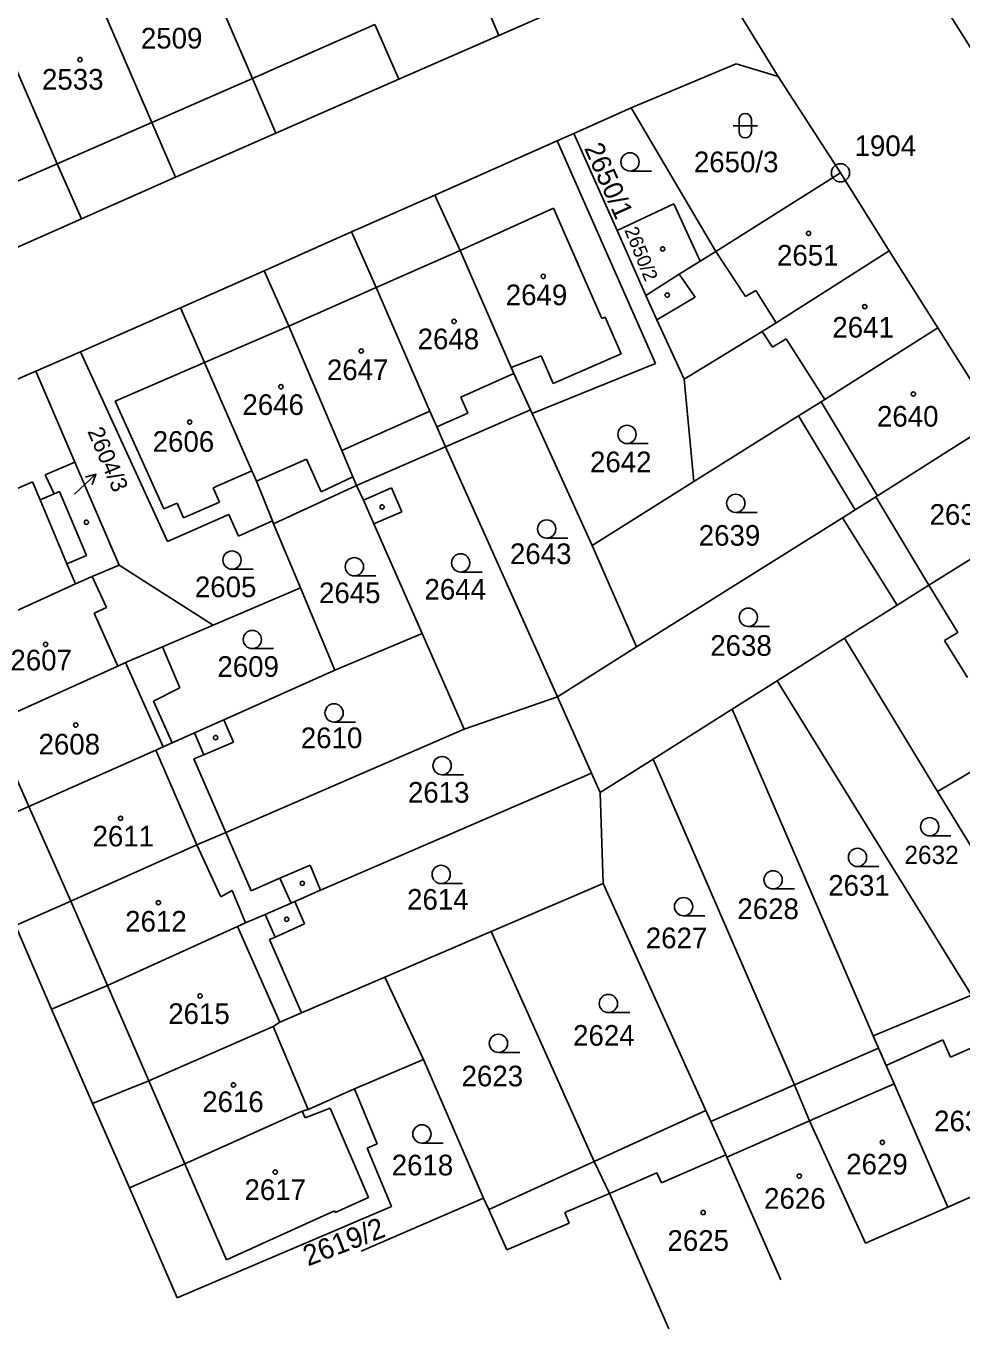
# Model space of a CAD drawing. Extents: x -822293 to -820259, y -1071573 to -1068794.
# Drawn here: x -820749.9 to -820673, y -1071339.5 to -1071232.4 of the extents above; entities that cross this region are included whole.
import ezdxf

# ---------------------------------------------------------------- set-up
doc = ezdxf.new("R2010")
doc.units = 0
for name, color, linetype in [('Vrstva 1', 7, 'Continuous'), ('Vrstva 16', 7, 'Continuous'), ('Vrstva 17', 7, 'Continuous'), ('Vrstva 18', 7, 'Continuous'), ('Vrstva 19', 7, 'Continuous'), ('Vrstva 2', 7, 'Continuous'), ('Vrstva 24', 7, 'Continuous'), ('Vrstva 25', 7, 'Continuous'), ('Vrstva 29', 7, 'Continuous'), ('Vrstva 3', 7, 'Continuous'), ('Vrstva 4', 7, 'Continuous')]:
    doc.layers.add(name, color=color, linetype=linetype)

msp = doc.modelspace()

# ---------------------------------------------------------------- linework, layer by layer
at = {"layer": 'Vrstva 1'}
for p, q in [((-820622.76, -1071313.08), (-820677.95, -1071225.19)), ((-820711.07, -1071233.22), (-820699.66, -1071228.17)), ((-820688.09, -1071236.58), (-820693.68, -1071227.51)), ((-820712.97, -1071228.69), (-820711.07, -1071233.22)), ((-820719.29, -1071236.82), (-820721.25, -1071232.32)), ((-820719.29, -1071236.82), (-820711.07, -1071233.22)), ((-820700.17, -1071239.16), (-820691.56, -1071235.54)), ((-820691.56, -1071235.54), (-820688.09, -1071236.58)), ((-820731.32, -1071236.74), (-820729.39, -1071241.25)), ((-820729.39, -1071241.25), (-820719.29, -1071236.82)), ((-820688.09, -1071236.58), (-820682.97, -1071244.51)), ((-820704.89, -1071241.27), (-820700.17, -1071239.16)), ((-820700.17, -1071239.16), (-820693.22, -1071250.97)), ((-820737.63, -1071244.87), (-820739.57, -1071240.36)), ((-820737.63, -1071244.87), (-820729.39, -1071241.25)), ((-820716.32, -1071246.34), (-820706.26, -1071241.88)), ((-820706.26, -1071241.88), (-820704.89, -1071241.27)), ((-820706.26, -1071241.88), (-820698.18, -1071260.18)), ((-820704.89, -1071241.27), (-820701.34, -1071249.26)), ((-820747.36, -1071243.77), (-820745.37, -1071248.28)), ((-820745.37, -1071248.28), (-820737.63, -1071244.87)), ((-820716.32, -1071246.34), (-820723.16, -1071249.37)), ((-820714.24, -1071250.9), (-820716.32, -1071246.34)), ((-820752.2, -1071251.29), (-820745.37, -1071248.28)), ((-820723.16, -1071249.37), (-820730.34, -1071252.56)), ((-820723.16, -1071249.37), (-820721.13, -1071253.93)), ((-820694.5, -1071251.77), (-820693.22, -1071250.97)), ((-820730.34, -1071252.56), (-820737.23, -1071255.6)), ((-820730.34, -1071252.56), (-820728.33, -1071257.1)), ((-820737.23, -1071255.6), (-820745.44, -1071259.22)), ((-820737.23, -1071255.6), (-820735.24, -1071260.1)), ((-820698.08, -1071256.59), (-820695.83, -1071261.47)), ((-820695.83, -1071261.47), (-820689.4, -1071257.55)), ((-820745.44, -1071259.22), (-820749.12, -1071260.8)), ((-820745.44, -1071259.22), (-820738.29, -1071274.8)), ((-820698.18, -1071260.18), (-820708.32, -1071264.29)), ((-820767.46, -1071268.84), (-820749.12, -1071260.8)), ((-820749.12, -1071260.8), (-820745.91, -1071268.3)), ((-820708.45, -1071264), (-820709.83, -1071260.99)), ((-820695.83, -1071261.47), (-820695.03, -1071269.89)), ((-820686.43, -1071264.49), (-820684.56, -1071263.32)), ((-820715.43, -1071267.03), (-820708.45, -1071264)), ((-820708.32, -1071264.29), (-820708.45, -1071264)), ((-820703.38, -1071275.13), (-820708.32, -1071264.29)), ((-820695.03, -1071269.89), (-820686.43, -1071264.49)), ((-820686.43, -1071264.49), (-820681.76, -1071272.2)), ((-820716.16, -1071265.39), (-820715.43, -1071267.03)), ((-820722.76, -1071270.2), (-820715.43, -1071267.03)), ((-820715.43, -1071267.03), (-820706.24, -1071287.59)), ((-820730.99, -1071269.84), (-820729.66, -1071273.12)), ((-820723.05, -1071269.5), (-820722.76, -1071270.2)), ((-820703.38, -1071275.13), (-820695.03, -1071269.89)), ((-820748.77, -1071271.39), (-820747.62, -1071270.9)), ((-820729.57, -1071273.35), (-820722.76, -1071270.2)), ((-820722.76, -1071270.2), (-820722.18, -1071271.42)), ((-820680.06, -1071271.14), (-820681.76, -1071272.2)), ((-820722.18, -1071271.42), (-820721.32, -1071273.37)), ((-820681.76, -1071272.2), (-820682.81, -1071272.87)), ((-820738.29, -1071274.8), (-820733.26, -1071272.58)), ((-820733.26, -1071272.58), (-820732.47, -1071274.36)), ((-820732.47, -1071274.36), (-820729.66, -1071273.12)), ((-820729.66, -1071273.12), (-820729.57, -1071273.35)), ((-820682.81, -1071272.87), (-820699.73, -1071283.48)), ((-820682.81, -1071272.87), (-820678.31, -1071280.04)), ((-820729.57, -1071273.35), (-820727.37, -1071278.63)), ((-820721.32, -1071273.37), (-820717.36, -1071282.38)), ((-820699.73, -1071283.48), (-820703.38, -1071275.13)), ((-820742.28, -1071276.75), (-820734.54, -1071281.69)), ((-820734.54, -1071281.69), (-820727.37, -1071278.63)), ((-820727.37, -1071278.63), (-820724.55, -1071285.39)), ((-820678.31, -1071280.04), (-820675.71, -1071278.4)), ((-820682.65, -1071282.77), (-820678.31, -1071280.04)), ((-820734.54, -1071281.69), (-820738.71, -1071283.48)), ((-820724.55, -1071285.39), (-820717.36, -1071282.38)), ((-820717.36, -1071282.38), (-820713.9, -1071290.24)), ((-820688.19, -1071286.27), (-820682.65, -1071282.77)), ((-820674.99, -1071295.36), (-820682.65, -1071282.77)), ((-820738.71, -1071283.48), (-820741.75, -1071284.76)), ((-820738.71, -1071283.48), (-820737.29, -1071286.84)), ((-820699.73, -1071283.48), (-820706.24, -1071287.59)), ((-820724.55, -1071285.39), (-820733.66, -1071289.48)), ((-820737.29, -1071286.84), (-820739.45, -1071287.95)), ((-820691.87, -1071288.59), (-820688.19, -1071286.27)), ((-820688.19, -1071286.27), (-820672.2, -1071312.09)), ((-820739.45, -1071287.95), (-820737.91, -1071291.37)), ((-820713.9, -1071290.24), (-820706.24, -1071287.59)), ((-820706.24, -1071287.59), (-820703.44, -1071293.85)), ((-820698.38, -1071292.7), (-820691.87, -1071288.59)), ((-820691.87, -1071288.59), (-820680.29, -1071315.45)), ((-820713.9, -1071290.24), (-820733.51, -1071298.72)), ((-820737.91, -1071291.37), (-820738.66, -1071291.7)), ((-820736.08, -1071290.55), (-820737.91, -1071291.37)), ((-820667.84, -1071291.16), (-820674.99, -1071295.36)), ((-820735.32, -1071292.35), (-820736.13, -1071292.69)), ((-820736.13, -1071292.69), (-820733.51, -1071298.72)), ((-820702.73, -1071295.45), (-820698.38, -1071292.7)), ((-820698.38, -1071292.7), (-820686.75, -1071319.48)), ((-820725.71, -1071303.48), (-820703.44, -1071293.85)), ((-820703.44, -1071293.85), (-820702.73, -1071295.45)), ((-820702.73, -1071295.45), (-820702.49, -1071302.92)), ((-820674.99, -1071295.36), (-820666.24, -1071309.73)), ((-820749.69, -1071296.59), (-820754.26, -1071298.59)), ((-820733.51, -1071298.72), (-820735.87, -1071299.74)), ((-820731.42, -1071303.52), (-820733.51, -1071298.72)), ((-820729.05, -1071302.49), (-820731.42, -1071303.52)), ((-820702.49, -1071302.92), (-820711.68, -1071306.87)), ((-820702.49, -1071302.92), (-820694.04, -1071321.59)), ((-820746.25, -1071304.37), (-820750.8, -1071306.39)), ((-820731.89, -1071306.16), (-820730.27, -1071305.46)), ((-820750.8, -1071306.39), (-820747.82, -1071313.25)), ((-820729.91, -1071307.54), (-820729.45, -1071307.33)), ((-820727.28, -1071313.55), (-820729.91, -1071307.54)), ((-820711.68, -1071306.87), (-820720.44, -1071310.62)), ((-820711.68, -1071306.87), (-820703.23, -1071325.77)), ((-820720.44, -1071310.62), (-820727.28, -1071313.55)), ((-820720.44, -1071310.62), (-820717.26, -1071317.38)), ((-820747.82, -1071313.25), (-820743.23, -1071311.31)), ((-820672.2, -1071312.09), (-820680.29, -1071315.45)), ((-820747.82, -1071313.25), (-820744.45, -1071321.01)), ((-820729.07, -1071314.32), (-820727.28, -1071313.55)), ((-820680.29, -1071315.45), (-820679.85, -1071316.45)), ((-820679.85, -1071316.45), (-820686.75, -1071319.48)), ((-820679.23, -1071317.88), (-820679.85, -1071316.45)), ((-820717.26, -1071317.38), (-820722.93, -1071319.81)), ((-820717.26, -1071317.38), (-820712.31, -1071328.8)), ((-820744.45, -1071321.01), (-820739.83, -1071319.14)), ((-820722.93, -1071319.81), (-820726.74, -1071321.49)), ((-820721.05, -1071324.33), (-820722.93, -1071319.81)), ((-820686.75, -1071319.48), (-820693.63, -1071322.49)), ((-820685.53, -1071322.44), (-820686.75, -1071319.48)), ((-820744.45, -1071321.01), (-820741.43, -1071327.94)), ((-820694.04, -1071321.59), (-820703.23, -1071325.77)), ((-820693.63, -1071322.49), (-820694.04, -1071321.59)), ((-820692.39, -1071325.23), (-820693.63, -1071322.49)), ((-820721.88, -1071324.68), (-820721.05, -1071324.33)), ((-820719.88, -1071329.48), (-820721.88, -1071324.68)), ((-820711.89, -1071329.72), (-820703.23, -1071325.77)), ((-820703.23, -1071325.77), (-820701.96, -1071328.4)), ((-820736.86, -1071325.98), (-820741.43, -1071327.94)), ((-820741.43, -1071327.94), (-820737.51, -1071336.97)), ((-820712.31, -1071328.8), (-820722.38, -1071333.16)), ((-820712.31, -1071328.8), (-820711.89, -1071329.72)), ((-820737.51, -1071336.97), (-820719.88, -1071329.48)), ((-820711.89, -1071329.72), (-820710.4, -1071333.04))]:
    msp.add_line(p, q, dxfattribs=at)
at = {"layer": 'Vrstva 16'}
msp.add_line((-820745.93, -1071270.92), (-820744.178, -1071269.28), dxfattribs=at)
msp.add_lwpolyline([(-820745.036, -1071269.534), (-820744.178, -1071269.28), (-820744.489, -1071270.118)], dxfattribs=at)
at = {"layer": 'Vrstva 2'}
for p, q in [((-820735.94, -1071226.03), (-820731.32, -1071236.74)), ((-820739.57, -1071240.36), (-820744.25, -1071229.56)), ((-820751.92, -1071233.24), (-820747.36, -1071243.77)), ((-820693.22, -1071250.97), (-820682.97, -1071244.51)), ((-820682.97, -1071244.51), (-820678.97, -1071250.92)), ((-820701.34, -1071249.26), (-820696.68, -1071247.06)), ((-820696.68, -1071247.06), (-820694.5, -1071251.77)), ((-820698.97, -1071254.58), (-820701.34, -1071249.26)), ((-820710.04, -1071260.52), (-820714.24, -1071250.9)), ((-820694.5, -1071251.77), (-820696.23, -1071252.85)), ((-820688.27, -1071256.84), (-820678.97, -1071250.92)), ((-820678.97, -1071250.92), (-820674.96, -1071257.25)), ((-820696.23, -1071252.85), (-820698.97, -1071254.58)), ((-820721.13, -1071253.93), (-820716.73, -1071264.1)), ((-820698.97, -1071254.58), (-820698.08, -1071256.59)), ((-820728.33, -1071257.1), (-820723.97, -1071267.34)), ((-820689.4, -1071257.55), (-820688.27, -1071256.84)), ((-820684.27, -1071263.14), (-820674.96, -1071257.25)), ((-820674.96, -1071257.25), (-820670.17, -1071264.87)), ((-820735.24, -1071260.1), (-820731.35, -1071269.01)), ((-820709.83, -1071260.99), (-820710.04, -1071260.52)), ((-820684.56, -1071263.32), (-820684.27, -1071263.14)), ((-820716.73, -1071264.1), (-820716.16, -1071265.39)), ((-820670.17, -1071264.87), (-820679.93, -1071271.06)), ((-820723.97, -1071267.34), (-820723.05, -1071269.5)), ((-820748.34, -1071269.34), (-820745.91, -1071268.3)), ((-820745.91, -1071268.3), (-820742.28, -1071276.75)), ((-820731.35, -1071269.01), (-820730.99, -1071269.84)), ((-820759.64, -1071274.41), (-820749.39, -1071269.91)), ((-820749.39, -1071269.91), (-820748.77, -1071271.39)), ((-820747.62, -1071270.9), (-820748.34, -1071269.34)), ((-820747.62, -1071270.9), (-820747.16, -1071270.71)), ((-820747.16, -1071270.71), (-820744.95, -1071275.96)), ((-820679.93, -1071271.06), (-820680.06, -1071271.14)), ((-820675.71, -1071278.4), (-820665.69, -1071272.14)), ((-820744.95, -1071275.96), (-820746.56, -1071276.64)), ((-820746.56, -1071276.64), (-820745.86, -1071278.3)), ((-820742.28, -1071276.75), (-820744.49, -1071277.7)), ((-820745.86, -1071278.3), (-820755.79, -1071282.82)), ((-820744.49, -1071277.7), (-820745.86, -1071278.3)), ((-820742.39, -1071285.05), (-820752.73, -1071289.74)), ((-820741.75, -1071284.76), (-820742.39, -1071285.05)), ((-820733.66, -1071289.48), (-820736.08, -1071290.55)), ((-820733.66, -1071289.48), (-820732.88, -1071291.32)), ((-820732.88, -1071291.32), (-820735.32, -1071292.35)), ((-820739.25, -1071291.96), (-820749.69, -1071296.59)), ((-820738.66, -1071291.7), (-820739.25, -1071291.96)), ((-820735.87, -1071299.74), (-820746.25, -1071304.37)), ((-820726.58, -1071301.41), (-820729.05, -1071302.49)), ((-820725.71, -1071303.48), (-820726.58, -1071301.41)), ((-820727.84, -1071304.41), (-820725.71, -1071303.48)), ((-820730.27, -1071305.46), (-820728.13, -1071304.54)), ((-820728.13, -1071304.54), (-820727.84, -1071304.41)), ((-820727.04, -1071306.24), (-820727.84, -1071304.41)), ((-820743.23, -1071311.31), (-820732.54, -1071306.45)), ((-820732.54, -1071306.45), (-820731.89, -1071306.16)), ((-820729.45, -1071307.33), (-820727.04, -1071306.24)), ((-820739.83, -1071319.14), (-820729.62, -1071314.67)), ((-820729.62, -1071314.67), (-820729.07, -1071314.32)), ((-820678.57, -1071319.39), (-820679.23, -1071317.88)), ((-820674.14, -1071329.52), (-820678.57, -1071319.39)), ((-820726.74, -1071321.49), (-820727.22, -1071321.65)), ((-820727.22, -1071321.65), (-820736.86, -1071325.98)), ((-820680.91, -1071332.5), (-820685.53, -1071322.44)), ((-820692.31, -1071325.41), (-820692.39, -1071325.23)), ((-820687.88, -1071335.5), (-820692.31, -1071325.41)), ((-820665.87, -1071325.89), (-820674.14, -1071329.52)), ((-820701.96, -1071328.4), (-820697.07, -1071339.54)), ((-820674.14, -1071329.52), (-820680.91, -1071332.5))]:
    msp.add_line(p, q, dxfattribs=at)
at = {"layer": 'Vrstva 24'}
for radius in [0.75, 0.0327]:
    msp.add_circle((-820682.97, -1071244.51), radius, dxfattribs=at)
at = {"layer": 'Vrstva 25'}
for p, q in [((-820691.3, -1071241.131), (-820691.3, -1071240.131)), ((-820690.3, -1071241.131), (-820690.3, -1071240.131)), ((-820691.8, -1071240.631), (-820689.8, -1071240.631)), ((-820698.52, -1071244.36), (-820700.27, -1071244.36)), ((-820698.77, -1071266.76), (-820700.52, -1071266.76)), ((-820689.83, -1071272.42), (-820691.58, -1071272.42)), ((-820705.38, -1071274.53), (-820707.13, -1071274.53)), ((-820731.24, -1071277.09), (-820732.99, -1071277.09)), ((-820712.44, -1071277.32), (-820714.19, -1071277.32)), ((-820721.18, -1071277.64), (-820722.93, -1071277.64)), ((-820688.8, -1071281.79), (-820690.55, -1071281.79)), ((-820729.57, -1071283.62), (-820731.32, -1071283.62)), ((-820722.85, -1071289.65), (-820724.6, -1071289.65)), ((-820713.97, -1071293.99), (-820715.72, -1071293.99)), ((-820673.89, -1071299.01), (-820675.64, -1071299.01)), ((-820679.82, -1071301.53), (-820681.57, -1071301.53)), ((-820714.05, -1071302.93), (-820715.8, -1071302.93)), ((-820686.76, -1071303.37), (-820688.51, -1071303.37)), ((-820694.12, -1071305.58), (-820695.87, -1071305.58)), ((-820700.3, -1071313.54), (-820702.05, -1071313.54)), ((-820709.34, -1071316.81), (-820711.09, -1071316.81)), ((-820715.63, -1071324.26), (-820717.38, -1071324.26))]:
    msp.add_line(p, q, dxfattribs=at)
for centre, radius in [((-820745.49, -1071235.2), 0.175), ((-820700.27, -1071243.61), 0.75), ((-820685.6, -1071249.48), 0.175), ((-820697.59, -1071250.76), 0.175), ((-820707.41, -1071253.02), 0.175), ((-820697.21, -1071254.56), 0.175), ((-820680.98, -1071255.51), 0.175), ((-820714.73, -1071256.72), 0.175), ((-820722.37, -1071259.15), 0.175), ((-820728.97, -1071262.09), 0.175), ((-820676.98, -1071262.69), 0.175), ((-820736.47, -1071265), 0.175), ((-820700.52, -1071266.01), 0.75), ((-820691.58, -1071271.67), 0.75), ((-820744.96, -1071273.23), 0.175), ((-820707.13, -1071273.78), 0.75), ((-820732.99, -1071276.34), 0.75), ((-820722.93, -1071276.89), 0.75), ((-820714.19, -1071276.57), 0.75), ((-820690.55, -1071281.04), 0.75), ((-820731.32, -1071282.87), 0.75), ((-820748.32, -1071283.27), 0.175), ((-820724.6, -1071288.9), 0.75), ((-820745.84, -1071289.9), 0.175), ((-820734.34, -1071290.93), 0.175), ((-820715.72, -1071293.24), 0.75), ((-820742.15, -1071297.57), 0.175), ((-820675.64, -1071298.26), 0.75), ((-820681.57, -1071300.78), 0.75), ((-820715.8, -1071302.18), 0.75), ((-820688.51, -1071302.62), 0.75), ((-820727.21, -1071302.91), 0.175), ((-820739.04, -1071304.5), 0.175), ((-820695.87, -1071304.83), 0.75), ((-820728.5, -1071305.86), 0.175), ((-820735.61, -1071312.16), 0.175), ((-820702.05, -1071312.79), 0.75), ((-820711.09, -1071316.06), 0.75), ((-820732.87, -1071319.48), 0.175), ((-820717.38, -1071323.51), 0.75), ((-820679.53, -1071324.21), 0.175), ((-820729.44, -1071326.65), 0.175), ((-820686.36, -1071326.98), 0.175), ((-820694.26, -1071329.97), 0.175)]:
    msp.add_circle(centre, radius, dxfattribs=at)
for centre, start, end in [((-820690.8, -1071240.131), 0, 180), ((-820690.8, -1071241.131), 180, 0)]:
    msp.add_arc(centre, 0.5, start, end, dxfattribs=at)
at = {"layer": 'Vrstva 29'}
msp.add_circle((-820720.65, -1071271.97), 0.175, dxfattribs=at)
at = {"layer": 'Vrstva 3'}
for p, q in [((-820721.25, -1071232.32), (-820731.32, -1071236.74)), ((-820731.32, -1071236.74), (-820739.57, -1071240.36)), ((-820739.57, -1071240.36), (-820747.36, -1071243.77)), ((-820747.36, -1071243.77), (-820754.18, -1071246.75)), ((-820714.24, -1071250.9), (-820706.56, -1071247.41)), ((-820702.6, -1071256.49), (-820706.56, -1071247.41)), ((-820721.13, -1071253.93), (-820714.24, -1071250.9)), ((-820693.22, -1071250.97), (-820690.78, -1071254.68)), ((-820696.23, -1071252.85), (-820694.92, -1071254.72)), ((-820728.33, -1071257.1), (-820721.13, -1071253.93)), ((-820694.92, -1071254.72), (-820698.08, -1071256.59)), ((-820690.78, -1071254.68), (-820689.94, -1071254.17)), ((-820689.94, -1071254.17), (-820688.27, -1071256.84)), ((-820735.24, -1071260.1), (-820728.33, -1071257.1)), ((-820702.32, -1071256.37), (-820702.6, -1071256.49)), ((-820701.01, -1071259.39), (-820702.32, -1071256.37)), ((-820689.4, -1071257.55), (-820688.56, -1071258.83)), ((-820688.56, -1071258.83), (-820687.44, -1071258.16)), ((-820687.44, -1071258.16), (-820684.27, -1071263.14)), ((-820706.59, -1071261.82), (-820701.01, -1071259.39)), ((-820742.61, -1071263.29), (-820735.24, -1071260.1)), ((-820710.04, -1071260.52), (-820707.58, -1071259.54)), ((-820707.58, -1071259.54), (-820706.59, -1071261.82)), ((-820714.19, -1071262.94), (-820709.83, -1071260.99)), ((-820742.61, -1071263.29), (-820738.6, -1071272.14)), ((-820713.6, -1071264.25), (-820714.19, -1071262.94)), ((-820684.56, -1071263.32), (-820679.93, -1071271.06)), ((-820723.97, -1071267.34), (-820716.73, -1071264.1)), ((-820716.16, -1071265.39), (-820713.6, -1071264.25)), ((-820734.54, -1071270.39), (-820731.35, -1071269.01)), ((-820730.99, -1071269.84), (-820726.88, -1071268.05)), ((-820726.88, -1071268.05), (-820725.67, -1071270.74)), ((-820725.67, -1071270.74), (-820723.05, -1071269.5)), ((-820734.03, -1071271.58), (-820734.54, -1071270.39)), ((-820680.06, -1071271.14), (-820675.71, -1071278.4)), ((-820746.56, -1071276.64), (-820748.77, -1071271.39)), ((-820738.6, -1071272.14), (-820737.51, -1071271.67)), ((-820737.51, -1071271.67), (-820736.99, -1071272.86)), ((-820736.99, -1071272.86), (-820734.03, -1071271.58)), ((-820744.49, -1071277.7), (-820743.3, -1071280.24)), ((-820675.71, -1071278.4), (-820673.32, -1071282.3)), ((-820743.3, -1071280.24), (-820744.32, -1071280.7)), ((-820744.32, -1071280.7), (-820742.39, -1071285.05)), ((-820673.32, -1071282.3), (-820674.43, -1071282.94)), ((-820674.43, -1071282.94), (-820672.52, -1071285.99)), ((-820741.75, -1071284.76), (-820738.66, -1071291.7)), ((-820749.69, -1071296.59), (-820752.73, -1071289.74)), ((-820736.08, -1071290.55), (-820735.32, -1071292.35)), ((-820739.25, -1071291.96), (-820735.87, -1071299.74)), ((-820746.25, -1071304.37), (-820749.69, -1071296.59)), ((-820735.87, -1071299.74), (-820733.9, -1071304.01)), ((-820729.05, -1071302.49), (-820728.13, -1071304.54)), ((-820743.23, -1071311.31), (-820746.25, -1071304.37)), ((-820733.9, -1071304.01), (-820732.98, -1071303.51)), ((-820732.98, -1071303.51), (-820731.89, -1071306.16)), ((-820730.27, -1071305.46), (-820729.45, -1071307.33)), ((-820732.54, -1071306.45), (-820729.07, -1071314.32)), ((-820739.83, -1071319.14), (-820743.23, -1071311.31)), ((-820729.62, -1071314.67), (-820726.74, -1071321.49)), ((-820679.23, -1071317.88), (-820674.56, -1071315.78)), ((-820674.56, -1071315.78), (-820673.92, -1071317.2)), ((-820673.92, -1071317.2), (-820670.53, -1071315.69)), ((-820736.86, -1071325.98), (-820739.83, -1071319.14)), ((-820685.53, -1071322.44), (-820678.57, -1071319.39)), ((-820726.97, -1071322.2), (-820724.93, -1071321.38)), ((-820724.93, -1071321.38), (-820721.78, -1071328.73)), ((-820727.22, -1071321.65), (-820726.97, -1071322.2)), ((-820692.31, -1071325.41), (-820685.53, -1071322.44)), ((-820697.68, -1071327.52), (-820692.39, -1071325.23)), ((-820733.44, -1071333.86), (-820736.86, -1071325.98)), ((-820701.96, -1071328.4), (-820698.06, -1071326.7)), ((-820698.06, -1071326.7), (-820697.68, -1071327.52)), ((-820721.78, -1071328.73), (-820724.5, -1071329.96)), ((-820705.64, -1071329.97), (-820701.96, -1071328.4)), ((-820724.56, -1071329.83), (-820733.44, -1071333.86)), ((-820724.5, -1071329.96), (-820724.56, -1071329.83)), ((-820705.27, -1071330.85), (-820705.64, -1071329.97)), ((-820710.4, -1071333.04), (-820705.27, -1071330.85))]:
    msp.add_line(p, q, dxfattribs=at)
at = {"layer": 'Vrstva 4'}
for p, q in [((-820722.18, -1071271.42), (-820719.89, -1071270.41)), ((-820719.89, -1071270.41), (-820719.03, -1071272.36)), ((-820719.03, -1071272.36), (-820721.32, -1071273.37))]:
    msp.add_line(p, q, dxfattribs=at)

# ---------------------------------------------------------------- texts
at = {"layer": 'Vrstva 16'}
for s, height, rotation, p in [('2604/3', 1.36, 293.01563, (-820744.9, -1071265.75)), ('2619/2', 1.7, 21.08564, (-820726.75, -1071334.41))]:
    msp.add_text(s, height=height, rotation=rotation, dxfattribs=at).set_placement(p)
at = {"layer": 'Vrstva 17'}
msp.add_text('1904', height=1.7, dxfattribs=at).set_placement((-820681.815, -1071243.13))
at = {"layer": 'Vrstva 18'}
msp.add_text('2650/1', height=1.6, rotation=293.95575, dxfattribs=at).set_placement((-820704.069, -1071242.471))
for s, height, p in [('2650/3', 1.7, (-820695.024, -1071244.46)), ('2642', 1.7, (-820703.562, -1071269.12)), ('2639', 1.7, (-820694.624, -1071275.16)), ('2643', 1.7, (-820710.144, -1071276.67)), ('2605', 1.7, (-820736.042, -1071279.39)), ('2645', 1.7, (-820725.839, -1071279.88)), ('2644', 1.7, (-820717.168, -1071279.59)), ('2638', 1.7, (-820693.678, -1071284.21)), ('2609', 1.7, (-820734.192, -1071285.94)), ('2610', 1.7, (-820727.334, -1071291.8)), ('2613', 1.7, (-820718.528, -1071296.28)), ('2632', 1.5, (-820677.718, -1071301.32)), ('2631', 1.7, (-820683.978, -1071303.93)), ('2614', 1.7, (-820718.6, -1071305.08)), ('2628', 1.7, (-820691.446, -1071305.85)), ('2627', 1.7, (-820698.978, -1071308.25)), ('2624', 1.7, (-820704.952, -1071316.26)), ('2623', 1.7, (-820714.12, -1071319.6)), ('2618', 1.7, (-820719.864, -1071326.92))]:
    msp.add_text(s, height=height, dxfattribs=at).set_placement(p)
at = {"layer": 'Vrstva 19'}
for s, p in [('2509', (-820740.482, -1071234.29)), ('2533', (-820748.612, -1071237.67)), ('2651', (-820688.192, -1071252.13)), ('2649', (-820710.488, -1071255.39)), ('2641', (-820683.64, -1071258.05)), ('2648', (-820717.732, -1071259.01)), ('2647', (-820725.192, -1071261.55)), ('2646', (-820732.138, -1071264.41)), ('2640', (-820679.972, -1071265.37)), ('2606', (-820739.512, -1071267.44)), ('2637', (-820675.649, -1071273.44)), ('2607', (-820751.206, -1071285.41)), ('2608', (-820748.895, -1071292.32)), ('2611', (-820744.454, -1071299.88)), ('2612', (-820741.776, -1071306.88)), ('2615', (-820738.232, -1071314.47)), ('2616', (-820735.44, -1071321.71)), ('2630', (-820675.278, -1071323.3)), ('2629', (-820682.502, -1071326.84)), ('2617', (-820731.965, -1071328.94)), ('2626', (-820689.252, -1071329.66)), ('2625', (-820697.194, -1071333.12))]:
    msp.add_text(s, height=1.7, dxfattribs=at).set_placement(p)
for s, height, rotation, p in [('2650/2', 1.139, 292.03839, (-820700.75, -1071249.21)), ('2604/3', 0.005, 293.24745, (-820745.935, -1071270.908))]:
    msp.add_text(s, height=height, rotation=rotation, dxfattribs=at).set_placement(p)

doc.saveas('drawing.dxf')
